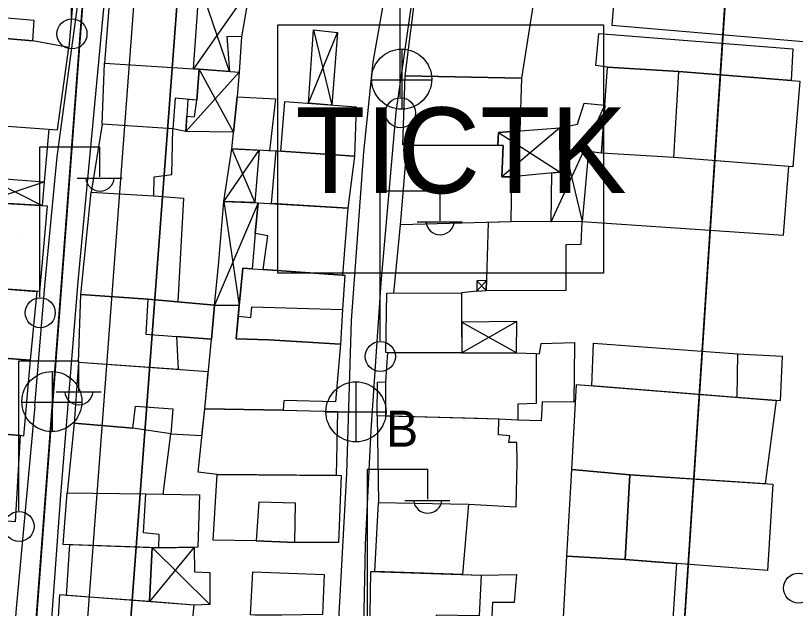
# Model space of a CAD drawing. Extents: x 417997 to 421451, y 4451742 to 4455216.
# Drawn here: x 419950.6 to 420041.5, y 4452779.7 to 4452848.9 of the extents above; entities that cross this region are included whole.
import ezdxf

# ---------------------------------------------------------------- set-up
doc = ezdxf.new("R2010")
doc.units = 0
for name, color, linetype in [('ADAKENARI', 7, 'Continuous'), ('B_Mesken', 7, 'Continuous'), ('B_Sundurma', 7, 'Continuous'), ('B_Teras', 7, 'Continuous'), ('Default', 7, 'Continuous'), ('KALDIRIM', 7, 'Continuous'), ('LJ_SEMBOL', 7, 'Continuous'), ('PL_REKRASYON', 7, 'Continuous'), ('PL_TURZM', 7, 'Continuous'), ('S_Elektrik_Diregi', 7, 'Continuous'), ('S_Rogar_Kapagi', 7, 'Continuous'), ('S_Rogar_Kapagi_Buski', 7, 'Continuous'), ('Sinir_Duvar_tek_tarafa_ait', 7, 'Continuous'), ('TR_PARKALANI', 7, 'Continuous'), ('TR_TİCK', 7, 'Continuous'), ('Yol_Sose', 7, 'Continuous')]:
    doc.layers.add(name, color=color, linetype=linetype)

# ---------------------------------------------------------------- blocks, each defined once
blk = doc.blocks.new('POINT_DISPLAY')
at = {"layer": 'Default'}
blk.add_line((0, 0), (0, 0), dxfattribs=at)

msp = doc.modelspace()

# ---------------------------------------------------------------- linework, layer by layer
at = {"layer": 'ADAKENARI'}
for p, q in [((419964.494, 4452931.329), (419950.327, 4452742.809)), ((419964.494, 4452931.329), (419950.327, 4452742.809)), ((419960.587, 4452732.559), (419974.93, 4452923.411)), ((419960.587, 4452732.559), (419974.93, 4452923.411)), ((420036.212, 4452894.7), (420026.691, 4452749.179)), ((420036.212, 4452894.7), (420026.691, 4452749.179))]:
    msp.add_line(p, q, dxfattribs=at)
at = {"layer": 'B_Mesken'}
for points in [[(419943.583, 4452850.518), (419943.941, 4452854.499), (419957.52, 4452853.221), (419956.808, 4452845.142), (419952.617, 4452845.925), (419943.039, 4452846.723)], [(419961.74, 4452853.276), (419960.951, 4452843.316), (419971.338, 4452842.643), (419972.035, 4452852.556)], [(420011.268, 4452852.435), (420009.574, 4452841.552), (419996.026, 4452841.825), (419997.383, 4452852.681), (419997.792, 4452852.58)], [(419943.039, 4452846.723), (419941.01, 4452846.953), (419940.073, 4452836.644), (419955.468, 4452835.521), (419956.808, 4452845.142), (419952.617, 4452845.925)], [(420019.6, 4452842.856), (420018.233, 4452843.029), (420018.584, 4452846.778), (420041.209, 4452844.962), (420040.997, 4452841.279), (420027.913, 4452842.328)], [(419970.673, 4452839.088), (419970.454, 4452835.338), (419968.942, 4452835.632), (419960.673, 4452836.205), (419960.951, 4452843.316), (419971.338, 4452842.643), (419971.982, 4452842.59), (419971.73, 4452838.988)], [(420027.332, 4452832.314), (420018.891, 4452832.799), (420019.6, 4452842.856), (420027.913, 4452842.328), (420042.009, 4452841.198), (420041.204, 4452831.22)], [(419996.229, 4452833.755), (419995.726, 4452833.762), (419996.026, 4452841.825), (420009.574, 4452841.552), (420009.363, 4452835.406), (420006.89, 4452835.22), (420006.819, 4452833.692)], [(419976.411, 4452839.371), (419980.879, 4452839.157), (419980.195, 4452833.094), (419975.799, 4452833.303)], [(419981.53, 4452833.032), (419981.99, 4452838.819), (419990.286, 4452838.225), (419990.117, 4452832.466)], [(419960.673, 4452836.205), (419959.409, 4452828.241), (419966.7, 4452827.825), (419966.757, 4452830.031), (419968.83, 4452830.327), (419968.942, 4452835.632)], [(419980.438, 4452826.929), (419980.967, 4452833.069), (419990.117, 4452832.466), (419989.334, 4452826.381)], [(419996.229, 4452833.755), (420007.437, 4452833.688), (420007.27, 4452830.048), (420008.395, 4452830.063), (420008.324, 4452824.805), (419995.452, 4452824.465)], [(420018.891, 4452832.799), (420017.406, 4452833.005), (420016.665, 4452824.819), (420040.134, 4452823.225), (420040.745, 4452831.257), (420027.332, 4452832.314)], [(419958.203, 4452816.313), (419959.409, 4452828.241), (419966.7, 4452827.825), (419970.163, 4452827.568), (419969.496, 4452815.466), (419966.016, 4452815.779)], [(419943.567, 4452820.384), (419941.425, 4452820.448), (419941.872, 4452827.382), (419954.287, 4452826.671), (419953.385, 4452816.669), (419947.021, 4452817.14), (419943.216, 4452817.373)], [(419979.452, 4452819.225), (419980.019, 4452823.16), (419978.528, 4452823.44), (419978.888, 4452827.025), (419989.334, 4452826.381), (419988.715, 4452818.567)], [(420005.698, 4452824.736), (420005.47, 4452816.799), (420014.766, 4452816.844), (420014.776, 4452822.165), (420016.524, 4452822.191), (420016.665, 4452824.819), (420008.324, 4452824.805)], [(419988.715, 4452818.567), (419988.995, 4452818.568), (419988.724, 4452814.566), (419988.484, 4452810.53), (419980.13, 4452811.036), (419976.331, 4452811.165), (419976.552, 4452813.798), (419976.671, 4452815.049), (419977.084, 4452819.393), (419978.188, 4452819.315), (419979.452, 4452819.225)], [(419953.087, 4452816.691), (419952.293, 4452808.644), (419941.255, 4452809.502), (419941.775, 4452817.463), (419943.216, 4452817.373), (419947.021, 4452817.14)], [(419969.342, 4452811.422), (419969.562, 4452807.566), (419957.912, 4452808.39), (419958.203, 4452816.313), (419966.016, 4452815.779), (419973.782, 4452815.082), (419973.424, 4452811.124)], [(419993.768, 4452809.574), (419993.886, 4452816.486), (420002.579, 4452816.535), (420002.623, 4452809.531)], [(419966.016, 4452815.779), (419965.765, 4452811.683), (419973.424, 4452811.124), (419973.782, 4452815.082)], [(419972.658, 4452802.987), (419973.424, 4452811.124), (419973.782, 4452815.082), (419976.671, 4452815.049), (419976.542, 4452813.69), (419976.331, 4452811.165), (419980.13, 4452811.036), (419988.484, 4452810.53), (419987.897, 4452803.783), (419981.863, 4452803.964), (419981.795, 4452802.821)], [(420011.865, 4452810.602), (420015.76, 4452810.74), (420015.745, 4452810.493), (420015.664, 4452803.746), (420011.966, 4452803.819), (420011.853, 4452801.602), (420009.163, 4452801.657), (420006.928, 4452801.776), (420004.435, 4452801.842), (419992.746, 4452802.152), (419992.783, 4452806.113), (419993.741, 4452806.127), (419993.976, 4452809.573), (420002.623, 4452809.531), (420004.653, 4452809.521), (420008.999, 4452809.5), (420011.302, 4452809.447), (420011.692, 4452809.391)], [(420039.953, 4452809.123), (420039.746, 4452803.905), (420039.255, 4452803.955), (420034.675, 4452804.322), (420017.758, 4452805.678), (420017.96, 4452810.645), (420034.744, 4452809.403)], [(419952.293, 4452808.644), (419951.531, 4452799.803), (419951.146, 4452799.875), (419941.05, 4452800.744), (419941.332, 4452804.88), (419944.135, 4452804.709), (419944.505, 4452809.249)], [(419973.066, 4452807.318), (419957.912, 4452808.39), (419957.424, 4452801.307), (419964.282, 4452800.72), (419964.576, 4452803.298), (419968.947, 4452802.996), (419968.708, 4452800.078), (419972.326, 4452799.861), (419972.658, 4452802.987), (419972.658, 4452802.987)], [(420015.998, 4452805.819), (420039.255, 4452803.955), (420037.998, 4452794.242), (420022.215, 4452795.284), (420015.452, 4452795.924)], [(419974.09, 4452795.338), (419971.875, 4452795.604), (419972.658, 4452802.987), (419981.795, 4452802.821), (419988.123, 4452802.669), (419987.962, 4452795.196)], [(419957.424, 4452801.307), (419956.611, 4452793.196), (419965.769, 4452793.064), (419967.805, 4452793.024), (419968.708, 4452800.078), (419964.282, 4452800.72)], [(420003.397, 4452791.871), (420008.953, 4452791.535), (420009.081, 4452796.669), (420009.035, 4452799.072), (420008.115, 4452799.071), (420008.2, 4452799.846), (420006.891, 4452799.939), (420006.928, 4452801.776), (419992.746, 4452802.152), (419992.891, 4452792.042)], [(419939.615, 4452790.788), (419940.147, 4452800.822), (419951.146, 4452799.875), (419950.546, 4452789.795)], [(420014.88, 4452785.797), (420015.452, 4452795.924), (420022.215, 4452795.284), (420021.644, 4452785.426)], [(419978.627, 4452787.594), (419973.618, 4452787.666), (419974.09, 4452795.338), (419988.546, 4452795.19), (419988.234, 4452787.406), (419983.138, 4452787.408)], [(420021.644, 4452785.426), (420022.215, 4452795.284), (420038.873, 4452794.184), (420038.259, 4452784.118)], [(419967.314, 4452786.775), (419956.127, 4452787.175), (419956.611, 4452793.196), (419965.769, 4452793.064), (419972.028, 4452792.941), (419971.824, 4452786.862)], [(419992.484, 4452784.005), (419992.891, 4452792.042), (420003.397, 4452791.871), (420002.715, 4452783.652)], [(419966.515, 4452786.803), (419966.21, 4452780.493), (419956.543, 4452781.224), (419956.933, 4452787.146)], [(420027.637, 4452784.954), (420026.983, 4452774.973), (420018.911, 4452775.624), (420014.324, 4452775.82), (420014.88, 4452785.797), (420021.644, 4452785.426)], [(419978, 4452778.943), (419978.242, 4452783.987), (419986.571, 4452783.659), (419986.371, 4452778.977), (419981.637, 4452778.921), (419978.479, 4452778.927)], [(420004.862, 4452783.578), (420008.983, 4452783.67), (420008.72, 4452780.398), (420006.203, 4452780.392), (420005.98, 4452775.712), (419999.571, 4452776.167), (419991.88, 4452776.55), (419992.004, 4452784.021), (419992.484, 4452784.005), (420002.715, 4452783.652)], [(419955.711, 4452781.286), (419955.369, 4452775.4), (419968.32, 4452774.809), (419968.519, 4452776.564), (419971.032, 4452776.35), (419971.433, 4452780.099)]]:
    msp.add_lwpolyline(points, close=True, dxfattribs=at)
at = {"layer": 'B_Sundurma'}
for p, q in [((419975.536, 4452842.333), (419972.035, 4452852.556)), ((419977.892, 4452852.014), (419971.338, 4452842.643)), ((419984.734, 4452838.622), (419988.14, 4452846.895)), ((419985.345, 4452847.199), (419987.475, 4452838.426)), ((419970.454, 4452835.338), (419976.653, 4452842.253)), ((419975.996, 4452835.252), (419971.982, 4452842.59)), ((420013.05, 4452824.813), (420019.285, 4452838.397)), ((420006.89, 4452835.22), (420014.082, 4452830.609)), ((420014.064, 4452835.758), (420007.27, 4452830.048)), ((420014.064, 4452835.758), (420016.665, 4452824.819)), ((419974.855, 4452827.184), (419979.003, 4452833.151)), ((419975.799, 4452833.303), (419978.494, 4452827.04)), ((419946.917, 4452827.093), (419953.938, 4452829.476)), ((419947.24, 4452829.976), (419953.683, 4452826.706)), ((419978.888, 4452827.025), (419973.782, 4452815.082)), ((419974.855, 4452827.184), (419976.671, 4452815.049)), ((420005.504, 4452817.971), (420004.352, 4452816.702)), ((420004.366, 4452817.913), (420005.47, 4452816.799)), ((420008.999, 4452809.5), (420002.6, 4452813.107)), ((420009.021, 4452813.171), (420002.623, 4452809.531)), ((419971.431, 4452786.855), (419966.21, 4452780.493)), ((419973.228, 4452780.147), (419966.515, 4452786.803))]:
    msp.add_line(p, q, dxfattribs=at)
for points in [[(419977.892, 4452852.014), (419976.931, 4452846.377), (419975.23, 4452846.41), (419975.536, 4452842.333), (419971.982, 4452842.59), (419971.338, 4452842.643), (419972.035, 4452852.556), (419974.643, 4452852.374)], [(419984.734, 4452838.622), (419985.345, 4452847.199), (419988.14, 4452846.895), (419987.475, 4452838.426)], [(419975.996, 4452835.252), (419970.454, 4452835.338), (419970.559, 4452837.143), (419971.46, 4452837.057), (419971.73, 4452838.988), (419971.982, 4452842.59), (419976.653, 4452842.253), (419976.411, 4452839.371)], [(420013.05, 4452824.813), (420013.109, 4452830.516), (420014.082, 4452830.609), (420014.064, 4452835.758), (420016.121, 4452836.197), (420016.874, 4452838.64), (420019.285, 4452838.397), (420018.891, 4452832.799), (420017.406, 4452833.005), (420016.665, 4452824.819)], [(420006.89, 4452835.22), (420014.064, 4452835.758), (420014.082, 4452830.609), (420008.395, 4452830.063), (420007.27, 4452830.048), (420007.437, 4452833.688), (420006.819, 4452833.692)], [(419974.855, 4452827.184), (419975.799, 4452833.303), (419979.003, 4452833.151), (419978.494, 4452827.04)], [(419946.917, 4452827.093), (419947.24, 4452829.976), (419953.938, 4452829.476), (419953.683, 4452826.706)], [(419974.26, 4452819.712), (419974.855, 4452827.184), (419978.888, 4452827.025), (419978.528, 4452823.44), (419978.188, 4452819.315), (419977.084, 4452819.393), (419976.671, 4452815.049), (419973.782, 4452815.082)], [(420005.504, 4452817.971), (420004.366, 4452817.913), (420004.352, 4452816.702), (420005.47, 4452816.799)], [(420008.999, 4452809.5), (420009.021, 4452813.171), (420002.6, 4452813.107), (420002.623, 4452809.531)], [(419971.431, 4452786.855), (419971.466, 4452783.972), (419973.241, 4452783.909), (419973.228, 4452780.147), (419971.433, 4452780.099), (419966.21, 4452780.493), (419966.515, 4452786.803), (419967.314, 4452786.775)]]:
    msp.add_lwpolyline(points, close=True, dxfattribs=at)
at = {"layer": 'B_Teras'}
for points in [[(419943.583, 4452850.518), (419943.039, 4452846.723), (419952.617, 4452845.925), (419952.763, 4452848.266), (419948.696, 4452848.64), (419948.808, 4452849.99)], [(419971.338, 4452842.643), (419971.982, 4452842.59), (419971.73, 4452838.988), (419969.215, 4452839.225), (419968.942, 4452835.632), (419960.673, 4452836.205), (419960.951, 4452843.316)], [(420027.332, 4452832.314), (420027.913, 4452842.328), (420042.009, 4452841.198), (420041.204, 4452831.22)], [(419976.552, 4452813.798), (419978.022, 4452813.65), (419978.135, 4452814.878), (419988.724, 4452814.566), (419988.484, 4452810.53), (419980.13, 4452811.036), (419976.331, 4452811.165)], [(420017.758, 4452805.678), (420017.96, 4452810.645), (420034.744, 4452809.403), (420034.675, 4452804.322)], [(420004.435, 4452801.842), (419993.745, 4452802.126), (419993.741, 4452806.127), (419993.976, 4452809.573), (420004.653, 4452809.521), (420008.999, 4452809.5), (420011.302, 4452809.447), (420011.277, 4452803.597), (420009.129, 4452803.543), (420009.163, 4452801.657), (420006.928, 4452801.776)], [(419965.516, 4452788.518), (419965.769, 4452793.064), (419972.028, 4452792.941), (419971.824, 4452786.862), (419967.314, 4452786.775), (419967.345, 4452788.323)], [(419983.211, 4452791.987), (419978.96, 4452792.118), (419978.627, 4452787.594), (419983.138, 4452787.408)], [(419991.88, 4452776.55), (419992.004, 4452784.021), (420004.862, 4452783.578), (420004.655, 4452778.856), (419999.64, 4452778.936), (419999.571, 4452776.167)]]:
    msp.add_lwpolyline(points, close=True, dxfattribs=at)
at = {"layer": 'KALDIRIM'}
msp.add_line((419955.193, 4452727.504), (419970.192, 4452927.076), dxfattribs=at)
msp.add_line((419955.193, 4452727.504), (419970.192, 4452927.076), dxfattribs=at)
at = {"layer": 'LJ_SEMBOL'}
msp.add_lwpolyline([(419981.187, 4452847.763), (420019.119, 4452847.763), (420019.119, 4452818.826), (419981.187, 4452818.826)], close=True, dxfattribs=at)
msp.add_lwpolyline([(419981.187, 4452847.763), (420019.119, 4452847.763), (420019.119, 4452818.826), (419981.187, 4452818.826)], close=True, dxfattribs=at)
at = {"layer": 'PL_REKRASYON'}
msp.add_lwpolyline([(419948.905, 4452723.895), (419950.327, 4452742.809), (419964.494, 4452931.329)], dxfattribs=at)
msp.add_lwpolyline([(419948.905, 4452723.895), (419950.327, 4452742.809), (419964.494, 4452931.329)], dxfattribs=at)
at = {"layer": 'PL_TURZM'}
msp.add_lwpolyline([(419960.587, 4452732.559), (419960.38, 4452729.805), (419964.833, 4452726.123), (420021.442, 4452741.416), (420026.595, 4452747.709), (420026.691, 4452749.179), (420036.212, 4452894.7), (420032.011, 4452901.811), (419979.832, 4452926.274), (419974.93, 4452923.411), (419960.587, 4452732.559)], dxfattribs=at)
msp.add_lwpolyline([(419960.587, 4452732.559), (419960.38, 4452729.805), (419964.833, 4452726.123), (420021.442, 4452741.416), (420026.595, 4452747.709), (420026.691, 4452749.179), (420036.212, 4452894.7), (420032.011, 4452901.811), (419979.832, 4452926.274), (419974.93, 4452923.411), (419960.587, 4452732.559)], dxfattribs=at)
at = {"layer": 'S_Elektrik_Diregi'}
for p, q in [((419957.134, 4452848.555), (419957.134, 4452866.055)), ((419995.433, 4452839.357), (419995.433, 4452856.857)), ((419953.436, 4452816.029), (419953.436, 4452833.529)), ((419953.436, 4452833.529), (419960.436, 4452833.529)), ((419960.436, 4452830.029), (419960.436, 4452833.529)), ((419957.776, 4452829.889), (419963.026, 4452829.889)), ((419993.083, 4452810.931), (419993.083, 4452828.431)), ((419993.083, 4452828.431), (420000.083, 4452828.431)), ((420000.083, 4452824.931), (420000.083, 4452828.431)), ((419997.423, 4452824.791), (420002.673, 4452824.791)), ((419950.972, 4452791.098), (419950.972, 4452808.598)), ((419950.972, 4452808.598), (419957.972, 4452808.598)), ((419957.972, 4452805.098), (419957.972, 4452808.598)), ((419955.312, 4452804.958), (419960.562, 4452804.958)), ((419991.64, 4452778.452), (419991.64, 4452795.952)), ((419991.64, 4452795.952), (419998.64, 4452795.952)), ((419998.64, 4452792.452), (419998.64, 4452795.952)), ((419995.98, 4452792.312), (420001.23, 4452792.312))]:
    msp.add_line(p, q, dxfattribs=at)
for centre in [(419957.17, 4452846.719), (419995.469, 4452837.522), (419953.472, 4452814.193), (419993.119, 4452809.095), (419951.008, 4452789.262), (420041.88, 4452782.069)]:
    msp.add_circle(centre, 1.75, dxfattribs=at)
for centre in [(419960.437, 4452830.042), (420000.084, 4452824.944), (419957.972, 4452805.111), (419998.641, 4452792.465)]:
    msp.add_arc(centre, 1.658, 184.83843, 355.14641, dxfattribs=at)
at = {"layer": 'S_Rogar_Kapagi'}
for p, q in [((419995.659, 4452837.913), (419995.659, 4452844.913)), ((419992.089, 4452841.378), (419999.089, 4452841.378)), ((419954.882, 4452800.298), (419954.882, 4452807.298)), ((419951.312, 4452803.763), (419958.312, 4452803.763))]:
    msp.add_line(p, q, dxfattribs=at)
for centre in [(419995.606, 4452841.441), (419954.828, 4452803.826)]:
    msp.add_circle(centre, 3.5, dxfattribs=at)
at = {"layer": 'S_Rogar_Kapagi_Buski'}
for p, q in [((419990.282, 4452806.134), (419990.282, 4452799.134)), ((419986.782, 4452802.634), (419993.782, 4452802.634))]:
    msp.add_line(p, q, dxfattribs=at)
msp.add_circle((419990.282, 4452802.634), 3.5, dxfattribs=at)
at = {"layer": 'Sinir_Duvar_tek_tarafa_ait'}
for points in [[(419976.931, 4452846.377), (419976.653, 4452842.253)], [(419954.471, 4452835.593), (419953.938, 4452829.476)], [(419981.108, 4452833.059), (419980.073, 4452833.1)], [(419994.691, 4452816.491), (419995.452, 4452824.465)], [(420004.352, 4452816.702), (420002.579, 4452816.535)]]:
    msp.add_lwpolyline(points, dxfattribs=at)
at = {"layer": 'TR_TİCK'}
for points in [[(420026.595, 4452747.709), (420026.691, 4452749.179), (420036.212, 4452894.7), (420032.011, 4452901.811), (419979.832, 4452926.274), (419974.93, 4452923.411), (419960.587, 4452732.559), (419960.38, 4452729.805), (419964.833, 4452726.123), (420021.442, 4452741.416), (420026.595, 4452747.709)], [(420026.595, 4452747.709), (420026.691, 4452749.179), (420036.212, 4452894.7), (420032.011, 4452901.811), (419979.832, 4452926.274), (419974.93, 4452923.411), (419960.587, 4452732.559), (419960.38, 4452729.805), (419964.833, 4452726.123), (420021.442, 4452741.416), (420026.595, 4452747.709)], [(419981.187, 4452818.826), (419981.187, 4452847.763), (420019.119, 4452847.763), (420019.119, 4452818.826), (419981.187, 4452818.826)], [(419981.187, 4452818.826), (419981.187, 4452847.763), (420019.119, 4452847.763), (420019.119, 4452818.826), (419981.187, 4452818.826)]]:
    msp.add_lwpolyline(points, dxfattribs=at)
at = {"layer": 'Yol_Sose'}
for points in [[(419952.835, 4452803.324), (419954.042, 4452817.745), (419955.453, 4452832.366), (419957.217, 4452845.628), (419959.496, 4452862.185), (419961.177, 4452876.965), (419962.994, 4452891.035), (419964.217, 4452905.973), (419965.917, 4452919.163), (419967.827, 4452931.192), (419968.655, 4452938.773), (419968.426, 4452939.219), (419956.884, 4452945.032), (419947.586, 4452948.47), (419946.592, 4452948.679), (419945.971, 4452948.586), (419943.128, 4452937.438), (419941.974, 4452921.312), (419940.64, 4452905.715), (419938.772, 4452895.003), (419937.44, 4452890.427), (419932.663, 4452881.606), (419927.573, 4452868.904), (419925.936, 4452856.942)], [(419957.89, 4452817.834), (419959.517, 4452835.17), (419960.904, 4452849.669), (419962.126, 4452862.994), (419965.729, 4452884.473), (419968.27, 4452906.658), (419971.85, 4452936.382), (419971.86, 4452936.513), (419972.032, 4452936.669), (419972.254, 4452936.792), (419972.712, 4452936.753), (419984.159, 4452931.312), (419999.08, 4452924.448)], [(419998.898, 4452924.532), (420003.316, 4452922.258), (420003.487, 4452921.983), (420003.665, 4452921.407), (420003.632, 4452920.428), (420002.223, 4452913.368), (420000.714, 4452900.847), (419997.968, 4452878.758), (419994.706, 4452857.335), (419992.262, 4452843.43), (419991.171, 4452832.937), (419989.714, 4452813.289), (419989.158, 4452795.453), (419988.062, 4452774.806), (419986.22, 4452752.749), (419985.292, 4452728.928), (419984.939, 4452725.493)], [(420023.438, 4452734.348), (419995.603, 4452728.099), (419989.813, 4452726.933), (419989.379, 4452727.007), (419989.043, 4452727.316), (419988.868, 4452727.738), (419988.681, 4452728.489), (419988.697, 4452733.704), (419989.835, 4452752.071), (419990.988, 4452767.711), (419991.376, 4452787.146), (419992.036, 4452800.498), (419993.197, 4452817.672), (419994.981, 4452837.6), (419997.502, 4452855.255)], [(420047.283, 4452850.1), (420046.904, 4452849.983), (420046.347, 4452849.965), (420020.455, 4452852.119), (420020.088, 4452847.732), (420043.33, 4452845.759), (420045.382, 4452845.496), (420046.158, 4452845.2), (420046.777, 4452844.761), (420047.217, 4452844.11)], [(419974.999, 4452716.912), (419964.873, 4452715.217), (419952.646, 4452714.403), (419952.307, 4452714.683), (419951.898, 4452715.517), (419951.666, 4452716.675), (419951.666, 4452717.89), (419951.028, 4452724.311), (419952.589, 4452745.825), (419954.283, 4452771.026), (419955.872, 4452792.926), (419957.89, 4452817.834)], [(419952.835, 4452803.324), (419950.608, 4452779.255), (419949.138, 4452752.803), (419948.125, 4452726.092), (419947.103, 4452716.449)]]:
    msp.add_lwpolyline(points, dxfattribs=at)

# ---------------------------------------------------------------- block references
at = {"layer": 'TR_PARKALANI', "xscale": 0.1, "yscale": 0.10000000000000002}
for p in [(419951.711, 4452846.16), (419951.711, 4452846.16), (419955.991, 4452845.152), (419955.991, 4452845.152), (419955.991, 4452836.126), (419955.991, 4452836.126), (419951.102, 4452822.964), (419951.102, 4452822.964), (419954.111, 4452816.382), (419954.111, 4452816.382), (419954.111, 4452807.357), (419954.111, 4452807.357), (419952.042, 4452783.476), (419952.042, 4452783.476)]:
    msp.add_blockref('POINT_DISPLAY', p, dxfattribs=at)

# ---------------------------------------------------------------- texts
at = {"layer": 'LJ_SEMBOL'}
msp.add_text('TICTK', height=10, dxfattribs=at).set_placement((419983.214, 4452828.146))
msp.add_text('TICTK', height=10, dxfattribs=at).set_placement((419983.214, 4452828.146))
at = {"layer": 'S_Rogar_Kapagi_Buski'}
msp.add_text('B', height=4.2, dxfattribs=at).set_placement((419993.782, 4452798.57))

doc.saveas('drawing.dxf')
